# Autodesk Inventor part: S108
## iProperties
Author: Administrator
Revision Number: A
Shininess: 41.0
PropertySet Name: _Private Model Information
Created: 2000-11
Part Number: S108
Project: ACME
Description: SCREW, PILOT
Document SubType Name: Modeling
Designer: E. MOSS
Control State: 0
Master: False
Checked Out: False
PropertySet Name: Design Tracking Control
Density: 0.0
Volumn: 0.0
Area: 0.0
PropertySet Name: Model Information
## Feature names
1. Revolution1
2. Revolution2
3. Chamfer1
